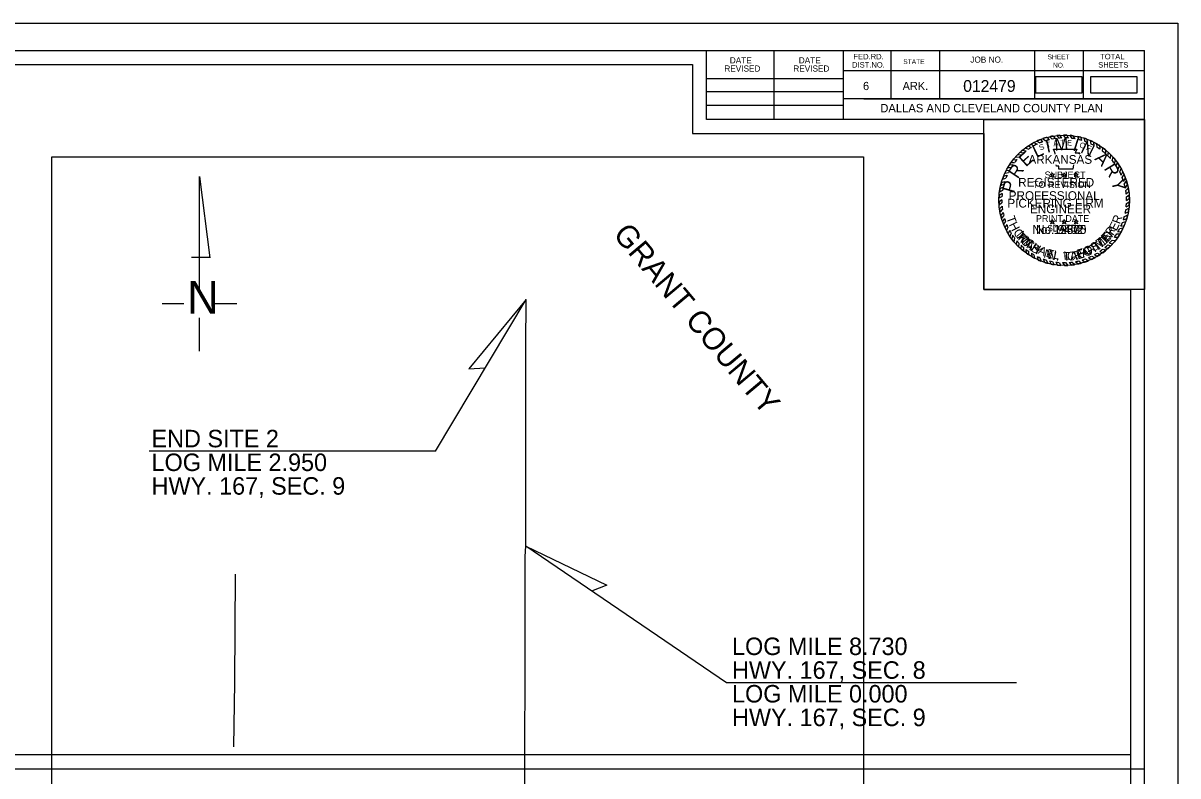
# Model space of a CAD drawing. Extents: x 10700 to 22009, y 10612 to 15552.
# Drawn here: x 12382 to 14033, y 14476 to 15552 of the extents above; entities that cross this region are included whole.
import ezdxf

# ---------------------------------------------------------------- set-up
doc = ezdxf.new("R2010")
doc.units = 0
for name, color, linetype in [('2', 7, 'Continuous'), ('30', 7, 'Continuous'), ('Default', 7, 'Continuous'), ('R_Border', 7, 'Continuous'), ('R_Border Notes', 7, 'Continuous'), ('R_Border Plan-Plan', 7, 'Continuous'), ('R_Dimension', 7, 'Continuous'), ('R_Draft', 7, 'Continuous'), ('R_No Plot', 7, 'Continuous'), ('STAMP_PE_CRAFTON', 7, 'Continuous'), ('STAMP_PE_FOSTER', 7, 'Continuous'), ('STAMP_PE_SEAL-INFO', 7, 'Continuous'), ('STAMP_PE_TAEGTMEYER', 7, 'Continuous'), ('STAMP_PE_TXT', 7, 'Continuous'), ('STAMP_PRELIMINARY', 7, 'Continuous')]:
    doc.layers.add(name, color=color, linetype=linetype)

msp = doc.modelspace()

# ---------------------------------------------------------------- linework, layer by layer
at = {"layer": '2'}
msp.add_lwpolyline([(12685.5, 14764.2), (12684.5, 14609.5), (12683.1, 14517.6)], dxfattribs=at)
at = {"layer": 'Default'}
for points in [[(13829.5, 15452.2), (13896.3, 15452.2), (13896.3, 15475.3), (13829.5, 15475.3)], [(13908.2, 15452.3), (13975, 15452.3), (13975, 15475.4), (13908.2, 15475.4)]]:
    msp.add_lwpolyline(points, close=True, dxfattribs=at)
msp.add_lwpolyline([(13099.8, 14460.6), (13099.7, 14517.2), (13100, 14620.5), (13100, 14789.6), (13100.8, 14804.2), (13100.8, 14933.5), (13100.8, 15053.8), (13101, 15089.9), (13101.7, 15157)], dxfattribs=at)
at = {"layer": 'R_Border'}
for p, q in [((10823.8, 15513.1), (13985.6, 15513.1)), ((13359.2, 15414.3), (13359.2, 15513.1)), ((13456, 15414.3), (13456, 15513.1)), ((13554.6, 15513.1), (13554.6, 15414.3)), ((13623, 15513.1), (13623, 15443.7)), ((13692.4, 15513.1), (13692.4, 15443.7)), ((13828.2, 15513.1), (13828.2, 15443.7)), ((13897.6, 15513.1), (13897.6, 15443.7)), ((13985.6, 13458.5), (13985.6, 15513.1)), ((13359.2, 15472.9), (13554.6, 15472.9)), ((13985.6, 15483.7), (13554.6, 15483.7)), ((13985.6, 15483.9), (13985.6, 15483.9)), ((13359.2, 15454.3), (13554.6, 15454.3)), ((13359.2, 15434.9), (13554.6, 15434.9)), ((13985.6, 15443.7), (13554.6, 15443.7)), ((13584.2, 15443.7), (13985.6, 15443.7)), ((13985.6, 15414.3), (13359.2, 15414.3))]:
    msp.add_line(p, q, dxfattribs=at)
at = {"layer": 'R_Border Plan-Plan'}
msp.add_line((10823.8, 14485.8), (13985.6, 14485.8), dxfattribs=at)
at = {"layer": 'R_Dimension'}
for p, q in [((12971.7, 14940.3), (12562.5, 14940.3)), ((13802.2, 14608.7), (13387.7, 14608.7))]:
    msp.add_line(p, q, dxfattribs=at)
for points in [[(12971.7, 14940.3), (13101.7, 15157), (13019.7, 15058), (13043.1, 15059.3)], [(13387.7, 14608.7), (13100.8, 14804.2), (13216.8, 14748.7), (13194.9, 14740)]]:
    msp.add_lwpolyline(points, dxfattribs=at)
at = {"layer": 'R_Draft'}
for p, q in [((12634.5, 15332.9), (12649.1, 15216.5)), ((12634.5, 15170.2), (12634.5, 15332.9)), ((12623.2, 15217.4), (12649.1, 15217.4)), ((12581, 15151), (12611.9, 15151)), ((12655.1, 15151), (12688, 15151)), ((12634.5, 15082.9), (12634.5, 15130.7))]:
    msp.add_line(p, q, dxfattribs=at)
at = {"layer": 'R_No Plot'}
msp.add_line((10699.8, 15552.1), (14033.1, 15552.1), dxfattribs=at)
for points in [[(10699.7, 15552.1), (14033.1, 15552.1), (14033.1, 13418.7), (10699.7, 13418.7)], [(10843.8, 15493.1), (13339.2, 15493.1), (13339.2, 15394.3), (13514.6, 15394.3), (13755.6, 15394.3), (13755.6, 15171), (13965.6, 15171), (13965.6, 13478.5), (10843.8, 13478.5)], [(13965.6, 14505.8), (10843.8, 14505.8), (10843.8, 15493.1), (13339.2, 15493.1), (13339.2, 15394.3), (13514.6, 15394.3), (13755.6, 15394.3), (13755.6, 15171), (13965.6, 15171)], [(13755.6, 15414.3), (13985.6, 15414.3), (13985.6, 15171), (13755.6, 15171)], [(12423.5, 15360.8), (13583.6, 15360.8), (13583.6, 13682.8), (12423.5, 13682.8)]]:
    msp.add_lwpolyline(points, close=True, dxfattribs=at)
at = {"layer": 'STAMP_PE_SEAL-INFO'}
for p, q in [((13836.7, 15385.6), (13839.7, 15382.4)), ((13840.2, 15386.9), (13844, 15383.8)), ((13846.1, 15388.7), (13849, 15385.2)), ((13850, 15389.7), (13853.6, 15386.2)), ((13854.8, 15390.6), (13857.8, 15387)), ((13860, 15391.4), (13862.8, 15387.5)), ((13867.3, 15387.8), (13864.2, 15391.8)), ((13872.3, 15387.9), (13869.5, 15392)), ((13876.9, 15387.7), (13874.3, 15391.9)), ((13882, 15387.2), (13879, 15391.6)), ((13886.2, 15386.5), (13883.6, 15391.1)), ((13891.8, 15385.3), (13890.1, 15389.9)), ((13895.9, 15384.2), (13894.3, 15388.9)), ((13900.4, 15382.8), (13899, 15387.6)), ((13904.6, 15381.2), (13903.1, 15386.1)), ((13811, 15370.5), (13816.3, 15369.4)), ((13814.8, 15373.7), (13819.4, 15371.7)), ((13819, 15376.4), (13823.4, 15374.4)), ((13822.9, 15378.8), (13827.2, 15376.6)), ((13827.4, 15381.3), (13832, 15379.1)), ((13831.7, 15383.5), (13835.6, 15380.7)), ((13855.4, 15371.7), (13888.8, 15371.7)), ((13856.6, 15368.6), (13855.4, 15371.7)), ((13888.8, 15371.7), (13886.5, 15366.8)), ((13909.2, 15379.1), (13908.1, 15384.1)), ((13913.6, 15376.8), (13912.8, 15381.9)), ((13917.5, 15374.6), (13917.1, 15379.6)), ((13921.8, 15371.7), (13921.5, 15376.9)), ((13925.5, 15369), (13925.8, 15373.9)), ((13929.9, 15365.3), (13930.1, 15370.5)), ((13794.8, 15353), (13799.8, 15352.9)), ((13797.6, 15356.7), (13803, 15356.9)), ((13801, 15360.8), (13806.2, 15360.4)), ((13804.2, 15364.2), (13809.7, 15363.8)), ((13807.6, 15367.5), (13812.2, 15366.1)), ((13857.6, 15365.6), (13856.6, 15368.6)), ((13857.7, 15364.5), (13857.6, 15365.6)), ((13886.5, 15366.8), (13892.9, 15366.8)), ((13892.9, 15366.8), (13891.4, 15364.5)), ((13933, 15362.4), (13933.7, 15367.4)), ((13936.6, 15358.7), (13937.3, 15363.9)), ((13939.4, 15355.5), (13940.7, 15360.2)), ((13942.6, 15351.3), (13944, 15356.3)), ((13944.8, 15348.2), (13946.6, 15352.8)), ((13785.8, 15337.4), (13790.8, 15338.4)), ((13787.7, 15341.3), (13792.6, 15341.9)), ((13790, 15345.5), (13794.9, 15345.7)), ((13792.4, 15349.5), (13797.6, 15349.9)), ((13859.6, 15347.4), (13859.3, 15349.6)), ((13862.7, 15347.4), (13859.6, 15347.4)), ((13862.7, 15343.1), (13862.7, 15347.4)), ((13883, 15343.1), (13862.7, 15343.1)), ((13883.2, 15346.5), (13883, 15343.1)), ((13884, 15349.6), (13883.2, 15346.5)), ((13947.9, 15343.2), (13949.7, 15348.1)), ((13949.9, 15339.5), (13952.2, 15344)), ((13952.2, 15334.7), (13954.5, 15339.5)), ((13779.8, 15319.9), (13784.5, 15321.8)), ((13780.9, 15324), (13785.6, 15325.7)), ((13782.4, 15329), (13787.3, 15330.4)), ((13783.9, 15333.1), (13789, 15334.5)), ((13953.6, 15331.3), (13956.2, 15335.7)), ((13955.5, 15325.8), (13958.3, 15330.6)), ((13956.6, 15322.2), (13959.6, 15326.7)), ((13958, 15316.6), (13961.1, 15321.1)), ((13781.7, 15304.2), (13777.4, 15301.7)), ((13782, 15308.5), (13777.7, 15305.7)), ((13782.6, 15312.8), (13778.2, 15310.6)), ((13783.5, 15317.4), (13778.8, 15314.9)), ((13958.6, 15312.8), (13962.2, 15316.3)), ((13959.3, 15307.7), (13963, 15311.1)), ((13959.6, 15303.5), (13963.5, 15306.4)), ((13781.5, 15299.3), (13777.4, 15296)), ((13781.6, 15295.2), (13777.6, 15292)), ((13781.9, 15290.3), (13778.2, 15286.7)), ((13958.7, 15285.3), (13963.2, 15287.5)), ((13959.2, 15289.2), (13963.6, 15291.8)), ((13959.6, 15294.3), (13963.8, 15297.1)), ((13959.8, 15298.3), (13963.8, 15301.6)), ((13782.4, 15286), (13778.9, 15282.3)), ((13783.2, 15281.4), (13779.8, 15277.7)), ((13784.1, 15277.2), (13781, 15273.1)), ((13785.4, 15272.7), (13782.4, 15268.6)), ((13955.3, 15270.9), (13960.2, 15272.9)), ((13956.8, 15275.8), (13961.5, 15277.8)), ((13957.8, 15280.3), (13962.4, 15282.3)), ((13786.8, 15268.5), (13784, 15264.4)), ((13788.4, 15264.3), (13785.8, 15260)), ((13790.2, 15260.4), (13787.9, 15255.8)), ((13792.5, 15255.8), (13790.6, 15250.9)), ((13947.5, 15253.6), (13952.5, 15254.1)), ((13950.2, 15258.6), (13955.1, 15259.3)), ((13951.8, 15261.9), (13956.7, 15262.9)), ((13953.9, 15267.1), (13958.8, 15268.4)), ((13794.9, 15251.8), (13793, 15247.1)), ((13796.9, 15248.7), (13795.8, 15243.2)), ((13799.7, 15244.8), (13798.7, 15239.5)), ((13802.7, 15241), (13801.9, 15235.8)), ((13805.8, 15237.6), (13805.1, 15232.4)), ((13935.4, 15237.6), (13940.2, 15236.7)), ((13939.3, 15241.9), (13943.9, 15241.1)), ((13942.4, 15245.8), (13947.4, 15245.9)), ((13945.7, 15250.8), (13950.5, 15250.7)), ((13809, 15234.4), (13808.7, 15229.1)), ((13812.4, 15231.2), (13812.4, 15226)), ((13816, 15228.3), (13816.2, 15223.1)), ((13819.4, 15225.8), (13819.8, 15220.6)), ((13823.7, 15223), (13824.3, 15217.9)), ((13827.2, 15220.9), (13828.1, 15215.8)), ((13913.9, 15220.9), (13918.1, 15218.5)), ((13918.1, 15223.3), (13922.6, 15221.4)), ((13921.5, 15225.6), (13925.9, 15223.7)), ((13926.1, 15229), (13930.8, 15227.6)), ((13928.8, 15231.3), (13933.5, 15230)), ((13932.9, 15235), (13937.3, 15233.6)), ((13832, 15218.4), (13833.6, 15213.2)), ((13835.7, 15216.7), (13837.5, 15211.6)), ((13840.6, 15214.8), (13842.7, 15209.8)), ((13844.7, 15213.5), (13847, 15208.6)), ((13849.8, 15212.1), (13851.9, 15207.4)), ((13853.8, 15211.2), (13856.3, 15206.6)), ((13858.8, 15210.4), (13861.2, 15206)), ((13863.2, 15209.9), (13865.9, 15205.7)), ((13868, 15209.7), (13871, 15205.5)), ((13872.6, 15209.6), (13876, 15205.7)), ((13877.8, 15209.9), (13881.1, 15206.1)), ((13882.2, 15210.4), (13885.9, 15206.8)), ((13886.6, 15211.1), (13890.5, 15207.7)), ((13891.6, 15212.1), (13895.3, 15208.9)), ((13896.2, 15213.4), (13900.3, 15210.4)), ((13901.1, 15215), (13905.5, 15212.3)), ((13905.3, 15216.6), (13909.5, 15214)), ((13909.9, 15218.7), (13914.7, 15216.6))]:
    msp.add_line(p, q, dxfattribs=at)
for radius, start, end in [(93.2, 111.3124, 114.7026), (93.2, 105.2339, 109.0352), (93.2, 99.7525, 102.7765), (89.1, 98.258, 101.0329), (93.2, 93.9381, 96.5517), (89.1, 92.1102, 95.0367), (93.2, 87.7298, 90.6707), (89.1, 85.9628, 88.9097), (93.2, 81.9732, 84.8236), (89.1, 79.9264, 82.696), (93.2, 75.3125, 77.9426), (93.2, 69.6061, 72.3058), (93.2, 129.7326, 132.5376), (89.1, 127.5297, 130.9683), (93.2, 123.6199, 126.5906), (89.1, 121.9746, 125.11), (93.2, 117.6544, 120.8099), (89.1, 115.6869, 119.1583), (89.1, 110.3086, 113.1659), (89.1, 104.0352, 107.3615), (89.1, 73.5575, 76.2314), (89.1, 67.6248, 70.504), (93.2, 63.1329, 66.2704), (89.1, 61.1558, 64.3784), (93.2, 56.9003, 60.0942), (89.1, 54.9238, 58.2702), (89.1, 48.3016, 52.0395), (93.2, 50.3492, 53.7159), (93.2, 141.6056, 144.4486), (89.1, 139.301, 142.5873), (93.2, 135.4021, 138.3031), (89.1, 133.1331, 136.2562), (89.1, 42.2212, 45.5512), (93.2, 44.3405, 47.3929), (89.1, 36.135, 39.5311), (93.2, 38.1247, 41.2316), (93.2, 31.9614, 35.4294), (93.2, 152.864, 155.5189), (93.2, 147.0072, 149.899), (89.1, 151.0315, 153.573), (89.1, 145.0197, 148.2104), (89.1, 29.9032, 33.6645), (89.1, 23.7732, 27.2211), (93.2, 25.9391, 29.0125), (93.2, 164.3068, 166.894), (93.2, 158.4077, 161.0701), (89.1, 162.4331, 165.0013), (89.1, 156.3402, 159.2319), (89.1, 17.6802, 21.4251), (93.2, 19.9538, 23.3141), (89.1, 11.5444, 15.2364), (93.2, 13.8421, 17.4447), (93.2, 175.7409, 178.2066), (93.2, 170.0003, 172.6878), (89.1, 173.73, 176.4734), (89.1, 167.9048, 170.9039), (89.1, 5.7599, 9.0606), (89.1, 359.7329, 3.0639), (93.2, 7.5852, 10.8621), (93.2, 1.7215, 4.7268), (93.2, 181.7251, 184.1626), (93.2, 187.4204, 190.1927), (89.1, 179.6454, 182.2633), (89.1, 185.4539, 188.234), (89.1, 353.8632, 357.1274), (93.2, 349.8305, 353.0885), (93.2, 355.7156, 358.9569), (93.2, 193.0369, 195.9973), (89.1, 191.2274, 193.9858), (89.1, 196.9675, 199.8353), (89.1, 341.777, 345.0925), (89.1, 348.0778, 351.3435), (93.2, 343.8925, 347.035), (93.2, 198.8967, 201.6281), (93.2, 204.5479, 207.4328), (89.1, 202.7761, 205.4791), (89.1, 208.7883, 211.7934), (89.1, 329.5549, 333.2076), (89.1, 335.6038, 339.1858), (93.2, 331.4037, 334.9332), (93.2, 337.3837, 340.9933), (93.2, 210.8636, 213.6571), (93.2, 216.6115, 219.491), (89.1, 214.1838, 217.2747), (89.1, 220.3909, 223.3056), (89.1, 316.6531, 320.3711), (93.2, 318.2846, 321.8043), (89.1, 323.5851, 327.4407), (93.2, 325.4405, 328.9872), (93.2, 222.48, 225.3801), (93.2, 228.3665, 231.348), (89.1, 226.2494, 229.2407), (89.1, 232.229, 234.9336), (93.2, 234.295, 236.9452), (89.1, 238.2223, 240.8353), (89.1, 299.0768, 302.1724), (93.2, 300.621, 303.8703), (89.1, 304.823, 308.5143), (93.2, 306.3721, 310.208), (89.1, 310.7744, 314.3161), (93.2, 312.4518, 315.6633), (93.2, 240.1977, 242.8613), (89.1, 244.3204, 246.9486), (93.2, 246.576, 249.1558), (89.1, 250.3491, 253.1216), (93.2, 252.5967, 255.3252), (89.1, 256.505, 259.1192), (93.2, 258.4433, 261.1398), (89.1, 262.3783, 265.2012), (93.2, 264.1978, 267.1009), (89.1, 268.3215, 271.277), (93.2, 270.2548, 273.3361), (89.1, 274.6157, 277.4486), (93.2, 276.4239, 279.4357), (89.1, 280.3459, 283.5814), (93.2, 282.3199, 285.3702), (89.1, 286.6423, 289.9783), (93.2, 288.5709, 291.9733), (89.1, 292.8745, 296.1185), (93.2, 294.6481, 298.2166)]:
    msp.add_arc((13870.6, 15298.8), radius, start, end, dxfattribs=at)
at = {"layer": 'STAMP_PE_TXT'}
for p, q in [((13852.4, 15334.5), (13850.4, 15335.9)), ((13850.4, 15335.9), (13852.9, 15335.9)), ((13852.9, 15335.9), (13853.6, 15338.2)), ((13853.6, 15338.2), (13854.4, 15335.9)), ((13854.4, 15335.9), (13856.9, 15335.9)), ((13856.9, 15335.9), (13854.9, 15334.5)), ((13869.4, 15334.5), (13867.4, 15335.9)), ((13867.4, 15335.9), (13869.9, 15335.9)), ((13869.9, 15335.9), (13870.6, 15338.2)), ((13870.6, 15338.2), (13871.4, 15335.9)), ((13871.4, 15335.9), (13873.8, 15335.9)), ((13873.8, 15335.9), (13871.8, 15334.5)), ((13886.4, 15334.5), (13884.4, 15335.9)), ((13884.4, 15335.9), (13886.8, 15335.9)), ((13886.8, 15335.9), (13887.6, 15338.2)), ((13887.6, 15338.2), (13888.4, 15335.9)), ((13888.4, 15335.9), (13890.8, 15335.9)), ((13890.8, 15335.9), (13888.8, 15334.5)), ((13851.7, 15332.1), (13852.4, 15334.5)), ((13853.6, 15333.6), (13851.7, 15332.1)), ((13855.6, 15332.1), (13853.6, 15333.6)), ((13854.9, 15334.5), (13855.6, 15332.1)), ((13868.6, 15332.1), (13869.4, 15334.5)), ((13870.6, 15333.6), (13868.6, 15332.1)), ((13872.6, 15332.1), (13870.6, 15333.6)), ((13871.8, 15334.5), (13872.6, 15332.1)), ((13885.6, 15332.1), (13886.4, 15334.5)), ((13887.6, 15333.6), (13885.6, 15332.1)), ((13889.6, 15332.1), (13887.6, 15333.6)), ((13888.8, 15334.5), (13889.6, 15332.1)), ((13852.9, 15268.8), (13853.6, 15271.2)), ((13853.6, 15271.2), (13854.4, 15268.8)), ((13869.9, 15268.8), (13870.6, 15271.2)), ((13870.6, 15271.2), (13871.4, 15268.8)), ((13886.8, 15268.8), (13887.6, 15271.2)), ((13887.6, 15271.2), (13888.4, 15268.8)), ((13852.4, 15267.4), (13850.4, 15268.8)), ((13850.4, 15268.8), (13852.9, 15268.8)), ((13851.7, 15265.1), (13852.4, 15267.4)), ((13853.6, 15266.5), (13851.7, 15265.1)), ((13855.6, 15265.1), (13853.6, 15266.5)), ((13854.4, 15268.8), (13856.9, 15268.8)), ((13856.9, 15268.8), (13854.9, 15267.4)), ((13854.9, 15267.4), (13855.6, 15265.1)), ((13869.4, 15267.4), (13867.4, 15268.8)), ((13867.4, 15268.8), (13869.9, 15268.8)), ((13868.6, 15265.1), (13869.4, 15267.4)), ((13870.6, 15266.5), (13868.6, 15265.1)), ((13872.6, 15265.1), (13870.6, 15266.5)), ((13871.4, 15268.8), (13873.8, 15268.8)), ((13873.8, 15268.8), (13871.8, 15267.4)), ((13871.8, 15267.4), (13872.6, 15265.1)), ((13886.4, 15267.4), (13884.4, 15268.8)), ((13884.4, 15268.8), (13886.8, 15268.8)), ((13885.6, 15265.1), (13886.4, 15267.4)), ((13887.6, 15266.5), (13885.6, 15265.1)), ((13889.6, 15265.1), (13887.6, 15266.5)), ((13888.4, 15268.8), (13890.8, 15268.8)), ((13890.8, 15268.8), (13888.8, 15267.4)), ((13888.8, 15267.4), (13889.6, 15265.1))]:
    msp.add_line(p, q, dxfattribs=at)
at = {"layer": 'STAMP_PRELIMINARY'}
msp.add_circle((13870.6, 15298.8), 93.2, dxfattribs=at)

# ---------------------------------------------------------------- texts
at = {"layer": '30'}
msp.add_text('GRANT COUNTY', height=31.68, rotation=310, dxfattribs=at).set_placement((13224.6, 15249.3))
at = {"layer": 'R_Border'}
for s, height, p in [('DATE', 8.79, (13392.6, 15494.5)), ('DATE', 8.79, (13491.2, 15494.5)), ('FED.RD.', 7.82, (13569.4, 15500.3)), ('JOB NO.', 8.79, (13736.4, 15495.5)), ('SHEET', 6.84, (13846.8, 15500.3)), ('TOTAL', 7.82, (13922, 15500.3)), ('REVISED', 8.79, (13384.8, 15482.7)), ('REVISED', 8.79, (13483.4, 15482.7)), ('DIST.NO.', 7.82, (13567.4, 15488.5)), ('STATE', 6.84, (13640.6, 15493.5)), ('NO.', 6.84, (13854.6, 15488.5)), ('SHEETS', 7.82, (13919.2, 15488.5)), ('6', 11.7, (13583, 15456.3)), ('ARK.', 11.72, (13639.6, 15456.3))]:
    msp.add_text(s, height=height, rotation=360, dxfattribs=at).set_placement(p)
at = {"layer": 'R_Border Notes'}
for s, height, p in [('012479', 16.8, (13726.2, 15453.8)), ('DALLAS AND CLEVELAND COUNTY PLAN', 12, (13607.7, 15424.5))]:
    msp.add_text(s, height=height, dxfattribs=at).set_placement(p)
at = {"layer": 'R_Dimension'}
for s, rotation, p in [('END SITE 2', 359.9994, (12566, 14945.6)), ('LOG MILE 2.950', 359.9994, (12566, 14911.7)), ('HWY. 167, SEC. 9', 359.9994, (12566, 14877.9)), ('LOG MILE 8.730', 359.9999, (13395.8, 14648.6)), ('HWY. 167, SEC. 8', 359.9999, (13395.8, 14614.7)), ('LOG MILE 0.000', 359.9999, (13395.8, 14580.8)), ('HWY. 167, SEC. 9', 359.9999, (13395.8, 14547))]:
    msp.add_text(s, height=25, rotation=rotation, dxfattribs=at).set_placement(p)
at = {"layer": 'R_Draft'}
msp.add_text('N', height=46.5, dxfattribs=at).set_placement((12616.9, 15136.7))
at = {"layer": 'STAMP_PE_CRAFTON'}
for s, rotation, p in [('T', 310.7442, (13800.3, 15247.7)), ('No. 12370', 360, (13825.2, 15250.7)), ('N', 49.2411, (13933.4, 15239)), ('O', 317.6422, (13807, 15239.6)), ('N', 324.4537, (13815.4, 15231.8)), ('T', 34.1136, (13916.4, 15225.1)), ('O', 41.8391, (13925, 15231.2)), ('Y', 331.1686, (13825.7, 15224.6)), ('N', 347.4752, (13846.3, 15215.5)), ('C', 6.0117, (13875.3, 15212.2)), ('R', 14.8189, (13886.3, 15213.3)), ('A', 20.5125, (13897.4, 15216.3)), ('F', 28.7821, (13907.2, 15220.1)), ('.', 356.8926, (13858.6, 15212.7))]:
    msp.add_text(s, height=12.5, rotation=rotation, dxfattribs=at).set_placement(p)
at = {"layer": 'STAMP_PE_FOSTER'}
for s, height, rotation, p in [('M', 12, 308.339, (13801.8, 15249)), ('No. 9402', 12.5, 360, (13830.5, 15250.7)), ('E', 12, 46.9613, (13930.6, 15238.7)), ('R', 12, 54.5031, (13937.9, 15246.9)), ('I', 12, 314.1842, (13809.8, 15239.6)), ('C', 12, 319.8733, (13813.3, 15236.1)), ('H', 12, 327.7235, (13822.6, 15228.7)), ('S', 12, 31.7234, (13912.5, 15224.9)), ('T', 12, 39.4194, (13922, 15231.2)), ('A', 12, 335.7276, (13832.4, 15222.9)), ('E', 12, 343.5779, (13843.8, 15218.2)), ('L', 12, 350.8115, (13854.4, 15215.4)), ('L', 12, 1.2666, (13869.8, 15213.8)), ('F', 12, 15.8691, (13891, 15216.3)), ('O', 12, 23.719, (13901.4, 15219.6)), ('.', 12, 6.8035, (13880.2, 15214.4))]:
    msp.add_text(s, height=height, rotation=rotation, dxfattribs=at).set_placement(p)
at = {"layer": 'STAMP_PE_TAEGTMEYER'}
for s, rotation, p in [('T', 289.646, (13787.6, 15273.9)), ('R', 69.57, (13950.1, 15263.9)), ('H', 296.7339, (13791.2, 15264)), ('O', 303.7708, (13797.1, 15252.9)), ('No. 19605', 360, (13825.2, 15250.7)), ('Y', 53.9986, (13938.4, 15244.7)), ('E', 63.0984, (13945.1, 15254.1)), ('M', 314.2033, (13803.6, 15243.4)), ('A', 321.0594, (13813.3, 15233.8)), ('T', 31.466, (13911.6, 15222.3)), ('M', 39.3, (13920.6, 15227.7)), ('E', 46.8094, (13931, 15236.5)), ('S', 327.8239, (13821.5, 15227.3)), ('N', 344.2727, (13840.5, 15217.3)), ('T', 3.0061, (13869.3, 15212)), ('A', 8.9826, (13879.7, 15212.5)), ('E', 17.6836, (13890.1, 15214.1)), ('G', 23.3052, (13900.6, 15217.4)), ('.', 350.6464, (13852.6, 15214))]:
    msp.add_text(s, height=12.5, rotation=rotation, dxfattribs=at).set_placement(p)
at = {"layer": 'STAMP_PE_TXT'}
for s, height, rotation, p in [('S', 7.81, 23.5541, (13836.6, 15369.8)), ('T', 7.81, 16.311, (13845.8, 15373.5)), ('A', 7.81, 9.0679, (13855.5, 15376)), ('T', 7.81, 1.8248, (13865.3, 15377.3)), ('E', 7.81, 355.2002, (13874.4, 15377.4)), ('O', 7.81, 342.2506, (13891.7, 15374.7)), ('F', 7.81, 335.0075, (13901.4, 15371.3)), ('ARKANSAS', 12.5, 360, (13819.5, 15350.9)), ('REGISTERED', 12.5, 360, (13804.8, 15318.2)), ('PROFESSIONAL', 12.5, 360, (13791.3, 15299.2)), ('ENGINEER', 12.5, 360, (13821.7, 15280.1))]:
    msp.add_text(s, height=height, rotation=rotation, dxfattribs=at).set_placement(p)
at = {"layer": 'STAMP_PRELIMINARY'}
for s, height, rotation, p in [('M', 18, 3.1074, (13857, 15369.7)), ('I', 18, 342.3164, (13881.7, 15370.4)), ('L', 18, 25.513, (13830.7, 15359)), ('I', 18, 12.5248, (13846, 15366.6)), ('N', 18, 333.9382, (13892.7, 15367.6)), ('E', 18, 42.3578, (13815.9, 15345.7)), ('A', 18, 315.6579, (13913.1, 15357.4)), ('R', 18, 56.2292, (13804.3, 15328.4)), ('SUBJECT', 9.6, 360, (13842.6, 15330.3)), ('R', 18, 301.3831, (13926.8, 15344.3)), ('P', 18, 73.913, (13798.8, 15308.2)), ('TO REVISION', 9.6, 360, (13826, 15316.4)), ('Y', 18, 283.2593, (13937.6, 15326.4)), ('PICKERING FIRM', 12.5, 360, (13789.4, 15288.4)), ('PRINT DATE', 9.6, 360, (13830.2, 15267.9)), ('$DATE$', 9.6, 360, (13847, 15254.1))]:
    msp.add_text(s, height=height, rotation=rotation, dxfattribs=at).set_placement(p)

doc.saveas('drawing.dxf')
